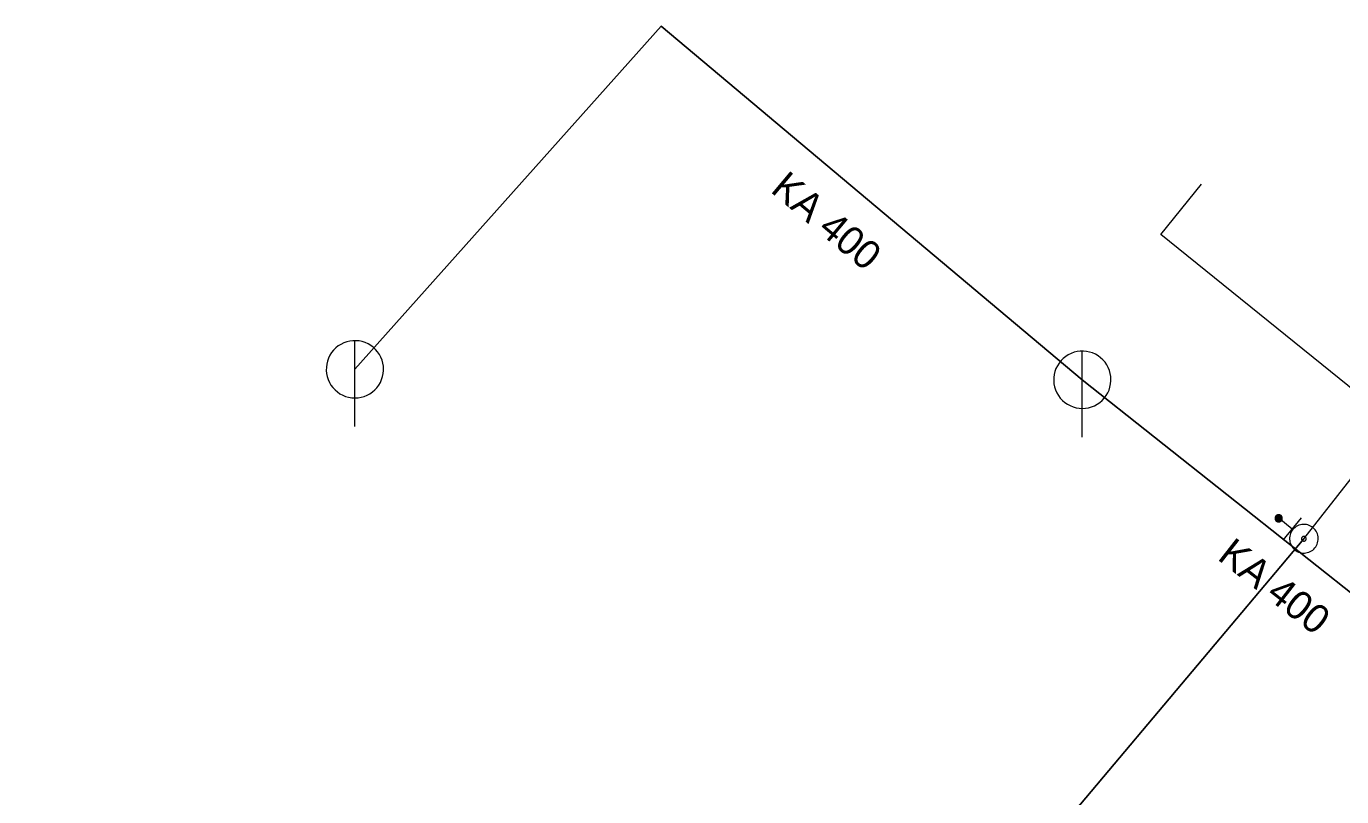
# Model space of a CAD drawing. Extents: x -790267 to -789874, y -989766 to -989454.
# Drawn here: x -790096.36 to -790050.43, y -989612.05 to -989585.16 of the extents above; entities that cross this region are included whole.
import ezdxf

# ---------------------------------------------------------------- set-up
doc = ezdxf.new("R2010")
doc.units = 0
doc.header["$LTSCALE"] = 0.4
doc.layers.add('1', color=7, linetype='Continuous')
for name, color, linetype, lineweight in [('13', 7, 'Continuous', 13), ('14', 7, 'Continuous', 13), ('17', 7, 'Continuous', 25), ('22', 7, 'Continuous', 13), ('34', 7, 'Continuous', 13), ('47', 7, 'Continuous', 13), ('9', 7, 'Continuous', 13)]:
    doc.layers.add(name, color=color, linetype=linetype, lineweight=lineweight)

msp = doc.modelspace()

# ---------------------------------------------------------------- linework, layer by layer
at = {"layer": '13'}
msp.add_lwpolyline([(-790051.752, -989603.049), (-790049.974, -989600.778), (-790048.645, -989598.973), (-790056.749, -989592.432), (-790055.327, -989590.667)], dxfattribs=at)
at = {"layer": '14', "lineweight": 25}
msp.add_line((-790059.488, -989597.498), (-790042.959, -989610.625), dxfattribs=at)
at = {"layer": '14'}
msp.add_line((-790052.165, -989602.709), (-790052.631, -989602.336), dxfattribs=at)
at = {"layer": '14', "lineweight": 25}
msp.add_lwpolyline([(-790084.884, -989597.134), (-790074.188, -989585.16), (-790059.488, -989597.498)], dxfattribs=at)
at = {"layer": '17'}
msp.add_lwpolyline([(-790096.357, -989656.872), (-790069.419, -989624.331), (-790067.352, -989621.572), (-790051.752, -989603.049)], dxfattribs=at)
at = {"layer": '22'}
for p, q in [((-790084.884, -989599.134), (-790084.883, -989596.134)), ((-790059.488, -989599.498), (-790059.487, -989596.498))]:
    msp.add_line(p, q, dxfattribs=at)
for points in [[(-790083.884, -989597.134), (-790083.889, -989597.025), (-790083.907, -989596.917), (-790083.937, -989596.811), (-790083.977, -989596.71), (-790084.029, -989596.613), (-790084.091, -989596.523), (-790084.163, -989596.44), (-790084.243, -989596.366), (-790084.331, -989596.3), (-790084.425, -989596.245), (-790084.525, -989596.2), (-790084.63, -989596.167), (-790084.737, -989596.145), (-790084.846, -989596.135), (-790084.956, -989596.137), (-790085.064, -989596.151), (-790085.171, -989596.176), (-790085.274, -989596.213), (-790085.372, -989596.262), (-790085.464, -989596.32), (-790085.55, -989596.389), (-790085.627, -989596.466), (-790085.696, -989596.552), (-790085.755, -989596.644), (-790085.803, -989596.742), (-790085.84, -989596.845), (-790085.866, -989596.952), (-790085.88, -989597.06), (-790085.883, -989597.17), (-790085.873, -989597.279), (-790085.852, -989597.386), (-790085.818, -989597.49), (-790085.774, -989597.59), (-790085.719, -989597.685), (-790085.653, -989597.773), (-790085.579, -989597.853), (-790085.496, -989597.925), (-790085.406, -989597.987), (-790085.31, -989598.039), (-790085.208, -989598.08), (-790085.103, -989598.11), (-790084.995, -989598.128), (-790084.885, -989598.134), (-790084.776, -989598.128), (-790084.668, -989598.11), (-790084.563, -989598.081), (-790084.461, -989598.04), (-790084.364, -989597.988), (-790084.274, -989597.926), (-790084.191, -989597.855), (-790084.116, -989597.775), (-790084.051, -989597.687), (-790083.995, -989597.593), (-790083.951, -989597.493), (-790083.917, -989597.389), (-790083.895, -989597.281), (-790083.885, -989597.172)], [(-790058.488, -989597.498), (-790058.493, -989597.389), (-790058.511, -989597.281), (-790058.541, -989597.175), (-790058.581, -989597.074), (-790058.633, -989596.977), (-790058.695, -989596.887), (-790058.767, -989596.804), (-790058.847, -989596.73), (-790058.935, -989596.664), (-790059.029, -989596.609), (-790059.129, -989596.564), (-790059.234, -989596.531), (-790059.341, -989596.509), (-790059.45, -989596.499), (-790059.56, -989596.501), (-790059.668, -989596.515), (-790059.775, -989596.54), (-790059.878, -989596.577), (-790059.976, -989596.626), (-790060.068, -989596.684), (-790060.154, -989596.753), (-790060.231, -989596.83), (-790060.3, -989596.916), (-790060.359, -989597.008), (-790060.407, -989597.106), (-790060.444, -989597.209), (-790060.47, -989597.316), (-790060.484, -989597.424), (-790060.487, -989597.534), (-790060.477, -989597.643), (-790060.456, -989597.75), (-790060.422, -989597.854), (-790060.378, -989597.954), (-790060.323, -989598.049), (-790060.257, -989598.137), (-790060.183, -989598.217), (-790060.1, -989598.289), (-790060.01, -989598.351), (-790059.914, -989598.403), (-790059.812, -989598.444), (-790059.707, -989598.474), (-790059.599, -989598.492), (-790059.489, -989598.498), (-790059.38, -989598.492), (-790059.272, -989598.474), (-790059.167, -989598.445), (-790059.065, -989598.404), (-790058.968, -989598.352), (-790058.878, -989598.29), (-790058.795, -989598.219), (-790058.72, -989598.139), (-790058.655, -989598.051), (-790058.599, -989597.957), (-790058.555, -989597.857), (-790058.521, -989597.753), (-790058.499, -989597.645), (-790058.489, -989597.536)]]:
    msp.add_lwpolyline(points, close=True, dxfattribs=at)
at = {"layer": '34'}
msp.add_line((-790051.848, -989602.322), (-790052.482, -989603.095), dxfattribs=at)
at = {"layer": '47'}
for points in [[(-790051.429, -989602.666), (-790051.471, -989602.635), (-790051.516, -989602.607), (-790051.563, -989602.586), (-790051.612, -989602.568), (-790051.664, -989602.556), (-790051.716, -989602.55), (-790051.768, -989602.55), (-790051.82, -989602.554), (-790051.871, -989602.563), (-790051.922, -989602.578), (-790051.97, -989602.599), (-790052.016, -989602.625), (-790052.059, -989602.654), (-790052.098, -989602.689), (-790052.134, -989602.726), (-790052.165, -989602.768), (-790052.193, -989602.813), (-790052.215, -989602.861), (-790052.232, -989602.909), (-790052.244, -989602.961), (-790052.25, -989603.013), (-790052.251, -989603.066), (-790052.247, -989603.118), (-790052.237, -989603.169), (-790052.222, -989603.219), (-790052.201, -989603.267), (-790052.176, -989603.313), (-790052.146, -989603.356), (-790052.111, -989603.395), (-790052.074, -989603.431), (-790052.032, -989603.462), (-790051.987, -989603.49), (-790051.94, -989603.512), (-790051.891, -989603.529), (-790051.839, -989603.541), (-790051.788, -989603.548), (-790051.735, -989603.549), (-790051.683, -989603.544), (-790051.631, -989603.534), (-790051.581, -989603.519), (-790051.533, -989603.498), (-790051.487, -989603.474), (-790051.444, -989603.443), (-790051.405, -989603.408), (-790051.369, -989603.371), (-790051.338, -989603.329), (-790051.31, -989603.284), (-790051.288, -989603.237), (-790051.271, -989603.188), (-790051.259, -989603.136), (-790051.252, -989603.085), (-790051.252, -989603.033), (-790051.256, -989602.981), (-790051.266, -989602.929), (-790051.281, -989602.878), (-790051.302, -989602.83), (-790051.327, -989602.785), (-790051.357, -989602.741), (-790051.392, -989602.702)], [(-790051.699, -989602.986), (-790051.706, -989602.98), (-790051.713, -989602.976), (-790051.72, -989602.973), (-790051.728, -989602.97), (-790051.737, -989602.968), (-790051.746, -989602.967), (-790051.754, -989602.966), (-790051.763, -989602.967), (-790051.771, -989602.969), (-790051.779, -989602.971), (-790051.788, -989602.975), (-790051.795, -989602.979), (-790051.802, -989602.984), (-790051.808, -989602.989), (-790051.814, -989602.996), (-790051.82, -989603.003), (-790051.824, -989603.01), (-790051.827, -989603.017), (-790051.83, -989603.025), (-790051.832, -989603.034), (-790051.833, -989603.043), (-790051.834, -989603.051), (-790051.833, -989603.06), (-790051.831, -989603.069), (-790051.829, -989603.076), (-790051.825, -989603.085), (-790051.821, -989603.092), (-790051.816, -989603.099), (-790051.811, -989603.105), (-790051.804, -989603.111), (-790051.797, -989603.117), (-790051.79, -989603.121), (-790051.783, -989603.124), (-790051.775, -989603.127), (-790051.766, -989603.129), (-790051.758, -989603.131), (-790051.749, -989603.131), (-790051.74, -989603.13), (-790051.731, -989603.128), (-790051.724, -989603.126), (-790051.715, -989603.122), (-790051.708, -989603.118), (-790051.701, -989603.113), (-790051.695, -989603.108), (-790051.689, -989603.101), (-790051.683, -989603.094), (-790051.679, -989603.087), (-790051.676, -989603.08), (-790051.673, -989603.072), (-790051.671, -989603.063), (-790051.669, -989603.055), (-790051.669, -989603.046), (-790051.67, -989603.037), (-790051.672, -989603.029), (-790051.674, -989603.021), (-790051.678, -989603.012), (-790051.682, -989603.005), (-790051.687, -989602.998), (-790051.692, -989602.992)]]:
    msp.add_lwpolyline(points, close=True, dxfattribs=at)
at = {"layer": '9'}
for points in [[(-790052.757, -989602.336), (-790052.757, -989602.349), (-790052.755, -989602.362), (-790052.752, -989602.375), (-790052.747, -989602.387), (-790052.741, -989602.399), (-790052.734, -989602.41), (-790052.726, -989602.42), (-790052.716, -989602.43), (-790052.706, -989602.438), (-790052.695, -989602.445), (-790052.683, -989602.451), (-790052.671, -989602.456), (-790052.658, -989602.459), (-790052.645, -989602.461), (-790052.632, -989602.463), (-790052.619, -989602.462), (-790052.606, -989602.46), (-790052.593, -989602.457), (-790052.581, -989602.452), (-790052.569, -989602.446), (-790052.558, -989602.439), (-790052.548, -989602.431), (-790052.538, -989602.421), (-790052.53, -989602.411), (-790052.523, -989602.4), (-790052.517, -989602.388), (-790052.512, -989602.376), (-790052.509, -989602.363), (-790052.507, -989602.35), (-790052.505, -989602.337), (-790052.506, -989602.324), (-790052.508, -989602.311), (-790052.511, -989602.298), (-790052.516, -989602.286), (-790052.522, -989602.274), (-790052.529, -989602.263), (-790052.537, -989602.253), (-790052.547, -989602.243), (-790052.557, -989602.235), (-790052.568, -989602.228), (-790052.58, -989602.222), (-790052.592, -989602.217), (-790052.605, -989602.214), (-790052.618, -989602.212), (-790052.631, -989602.211), (-790052.644, -989602.211), (-790052.657, -989602.213), (-790052.67, -989602.216), (-790052.682, -989602.221), (-790052.694, -989602.227), (-790052.705, -989602.234), (-790052.715, -989602.242), (-790052.725, -989602.252), (-790052.733, -989602.262), (-790052.74, -989602.273), (-790052.746, -989602.285), (-790052.751, -989602.297), (-790052.754, -989602.31), (-790052.756, -989602.323)], [(-790052.737, -989602.336), (-790052.738, -989602.347), (-790052.736, -989602.358), (-790052.733, -989602.369), (-790052.729, -989602.379), (-790052.724, -989602.389), (-790052.718, -989602.398), (-790052.711, -989602.407), (-790052.703, -989602.415), (-790052.694, -989602.422), (-790052.685, -989602.428), (-790052.675, -989602.433), (-790052.665, -989602.437), (-790052.654, -989602.44), (-790052.643, -989602.443), (-790052.632, -989602.443), (-790052.621, -989602.443), (-790052.61, -989602.441), (-790052.599, -989602.438), (-790052.589, -989602.434), (-790052.579, -989602.429), (-790052.57, -989602.423), (-790052.561, -989602.416), (-790052.553, -989602.408), (-790052.546, -989602.399), (-790052.54, -989602.39), (-790052.535, -989602.38), (-790052.531, -989602.37), (-790052.528, -989602.359), (-790052.526, -989602.348), (-790052.525, -989602.337), (-790052.525, -989602.326), (-790052.527, -989602.315), (-790052.53, -989602.304), (-790052.534, -989602.294), (-790052.539, -989602.284), (-790052.545, -989602.275), (-790052.552, -989602.266), (-790052.56, -989602.258), (-790052.569, -989602.251), (-790052.578, -989602.245), (-790052.588, -989602.24), (-790052.598, -989602.236), (-790052.609, -989602.233), (-790052.62, -989602.231), (-790052.631, -989602.231), (-790052.642, -989602.23), (-790052.653, -989602.232), (-790052.664, -989602.235), (-790052.674, -989602.239), (-790052.684, -989602.244), (-790052.693, -989602.25), (-790052.702, -989602.257), (-790052.71, -989602.265), (-790052.717, -989602.274), (-790052.723, -989602.283), (-790052.728, -989602.293), (-790052.732, -989602.303), (-790052.735, -989602.314), (-790052.737, -989602.325)], [(-790052.718, -989602.336), (-790052.718, -989602.345), (-790052.717, -989602.354), (-790052.714, -989602.363), (-790052.711, -989602.371), (-790052.707, -989602.379), (-790052.702, -989602.387), (-790052.696, -989602.394), (-790052.69, -989602.4), (-790052.683, -989602.406), (-790052.675, -989602.411), (-790052.667, -989602.415), (-790052.659, -989602.418), (-790052.65, -989602.421), (-790052.641, -989602.422), (-790052.632, -989602.424), (-790052.623, -989602.423), (-790052.614, -989602.422), (-790052.605, -989602.419), (-790052.597, -989602.416), (-790052.589, -989602.412), (-790052.581, -989602.407), (-790052.574, -989602.401), (-790052.568, -989602.395), (-790052.562, -989602.388), (-790052.557, -989602.38), (-790052.553, -989602.372), (-790052.55, -989602.364), (-790052.547, -989602.355), (-790052.546, -989602.346), (-790052.544, -989602.337), (-790052.545, -989602.328), (-790052.546, -989602.319), (-790052.549, -989602.31), (-790052.552, -989602.302), (-790052.556, -989602.294), (-790052.561, -989602.286), (-790052.567, -989602.279), (-790052.573, -989602.273), (-790052.58, -989602.267), (-790052.588, -989602.262), (-790052.596, -989602.258), (-790052.604, -989602.255), (-790052.613, -989602.252), (-790052.622, -989602.251), (-790052.631, -989602.25), (-790052.64, -989602.25), (-790052.649, -989602.251), (-790052.658, -989602.254), (-790052.666, -989602.257), (-790052.674, -989602.261), (-790052.682, -989602.266), (-790052.689, -989602.272), (-790052.695, -989602.278), (-790052.701, -989602.285), (-790052.706, -989602.293), (-790052.71, -989602.301), (-790052.713, -989602.309), (-790052.716, -989602.318), (-790052.717, -989602.327)], [(-790052.698, -989602.336), (-790052.698, -989602.343), (-790052.697, -989602.35), (-790052.696, -989602.357), (-790052.693, -989602.363), (-790052.69, -989602.369), (-790052.686, -989602.375), (-790052.682, -989602.381), (-790052.677, -989602.386), (-790052.671, -989602.39), (-790052.665, -989602.394), (-790052.659, -989602.397), (-790052.653, -989602.4), (-790052.646, -989602.401), (-790052.639, -989602.404), (-790052.632, -989602.404), (-790052.625, -989602.404), (-790052.618, -989602.402), (-790052.611, -989602.401), (-790052.605, -989602.398), (-790052.598, -989602.395), (-790052.593, -989602.391), (-790052.587, -989602.387), (-790052.582, -989602.382), (-790052.578, -989602.376), (-790052.574, -989602.37), (-790052.571, -989602.364), (-790052.568, -989602.358), (-790052.566, -989602.351), (-790052.565, -989602.344), (-790052.564, -989602.337), (-790052.564, -989602.33), (-790052.565, -989602.323), (-790052.567, -989602.316), (-790052.57, -989602.31), (-790052.573, -989602.303), (-790052.577, -989602.298), (-790052.581, -989602.292), (-790052.586, -989602.287), (-790052.592, -989602.283), (-790052.597, -989602.279), (-790052.604, -989602.276), (-790052.61, -989602.273), (-790052.617, -989602.271), (-790052.624, -989602.27), (-790052.631, -989602.27), (-790052.638, -989602.27), (-790052.645, -989602.27), (-790052.652, -989602.272), (-790052.658, -989602.275), (-790052.664, -989602.278), (-790052.67, -989602.282), (-790052.676, -989602.286), (-790052.681, -989602.291), (-790052.685, -989602.297), (-790052.689, -989602.302), (-790052.692, -989602.309), (-790052.695, -989602.315), (-790052.696, -989602.322), (-790052.698, -989602.329)], [(-790052.678, -989602.336), (-790052.678, -989602.341), (-790052.678, -989602.346), (-790052.677, -989602.351), (-790052.675, -989602.355), (-790052.673, -989602.36), (-790052.67, -989602.364), (-790052.667, -989602.367), (-790052.663, -989602.371), (-790052.66, -989602.374), (-790052.656, -989602.377), (-790052.651, -989602.379), (-790052.647, -989602.381), (-790052.642, -989602.382), (-790052.637, -989602.384), (-790052.632, -989602.384), (-790052.627, -989602.384), (-790052.622, -989602.383), (-790052.617, -989602.382), (-790052.613, -989602.38), (-790052.608, -989602.378), (-790052.604, -989602.375), (-790052.6, -989602.372), (-790052.597, -989602.368), (-790052.594, -989602.365), (-790052.591, -989602.361), (-790052.589, -989602.356), (-790052.587, -989602.352), (-790052.586, -989602.347), (-790052.585, -989602.342), (-790052.584, -989602.337), (-790052.584, -989602.332), (-790052.585, -989602.327), (-790052.586, -989602.322), (-790052.588, -989602.318), (-790052.59, -989602.313), (-790052.593, -989602.309), (-790052.596, -989602.305), (-790052.599, -989602.302), (-790052.603, -989602.299), (-790052.607, -989602.296), (-790052.612, -989602.294), (-790052.616, -989602.292), (-790052.621, -989602.291), (-790052.626, -989602.29), (-790052.631, -989602.29), (-790052.636, -989602.29), (-790052.641, -989602.291), (-790052.646, -989602.291), (-790052.65, -989602.293), (-790052.655, -989602.295), (-790052.659, -989602.298), (-790052.662, -989602.301), (-790052.666, -989602.304), (-790052.669, -989602.308), (-790052.672, -989602.312), (-790052.674, -989602.317), (-790052.676, -989602.321), (-790052.677, -989602.326), (-790052.678, -989602.331)], [(-790052.658, -989602.336), (-790052.658, -989602.339), (-790052.659, -989602.342), (-790052.658, -989602.344), (-790052.657, -989602.347), (-790052.656, -989602.35), (-790052.654, -989602.352), (-790052.652, -989602.354), (-790052.65, -989602.356), (-790052.648, -989602.358), (-790052.646, -989602.36), (-790052.643, -989602.362), (-790052.64, -989602.363), (-790052.638, -989602.363), (-790052.635, -989602.364), (-790052.632, -989602.364), (-790052.629, -989602.364), (-790052.626, -989602.364), (-790052.623, -989602.363), (-790052.621, -989602.362), (-790052.618, -989602.361), (-790052.616, -989602.359), (-790052.613, -989602.357), (-790052.611, -989602.355), (-790052.61, -989602.353), (-790052.608, -989602.351), (-790052.607, -989602.348), (-790052.605, -989602.345), (-790052.605, -989602.343), (-790052.604, -989602.34), (-790052.603, -989602.337), (-790052.604, -989602.334), (-790052.604, -989602.331), (-790052.605, -989602.328), (-790052.606, -989602.326), (-790052.607, -989602.323), (-790052.609, -989602.321), (-790052.61, -989602.318), (-790052.612, -989602.316), (-790052.615, -989602.315), (-790052.617, -989602.313), (-790052.62, -989602.312), (-790052.622, -989602.311), (-790052.625, -989602.31), (-790052.628, -989602.31), (-790052.631, -989602.309), (-790052.634, -989602.31), (-790052.637, -989602.309), (-790052.639, -989602.311), (-790052.642, -989602.311), (-790052.645, -989602.312), (-790052.647, -989602.314), (-790052.649, -989602.315), (-790052.651, -989602.317), (-790052.653, -989602.32), (-790052.655, -989602.322), (-790052.656, -989602.325), (-790052.657, -989602.327), (-790052.658, -989602.33), (-790052.658, -989602.333)], [(-790052.639, -989602.336), (-790052.639, -989602.338), (-790052.639, -989602.338), (-790052.638, -989602.338), (-790052.638, -989602.34), (-790052.639, -989602.341), (-790052.637, -989602.341), (-790052.637, -989602.341), (-790052.637, -989602.343), (-790052.637, -989602.343), (-790052.636, -989602.344), (-790052.634, -989602.344), (-790052.634, -989602.344), (-790052.634, -989602.345), (-790052.632, -989602.345), (-790052.632, -989602.345), (-790052.631, -989602.345), (-790052.63, -989602.345), (-790052.63, -989602.344), (-790052.629, -989602.344), (-790052.627, -989602.344), (-790052.627, -989602.343), (-790052.627, -989602.343), (-790052.626, -989602.342), (-790052.626, -989602.342), (-790052.624, -989602.341), (-790052.624, -989602.34), (-790052.623, -989602.339), (-790052.623, -989602.339), (-790052.623, -989602.338), (-790052.623, -989602.337), (-790052.623, -989602.336), (-790052.623, -989602.335), (-790052.623, -989602.335), (-790052.624, -989602.334), (-790052.624, -989602.333), (-790052.625, -989602.332), (-790052.625, -989602.332), (-790052.626, -989602.331), (-790052.626, -989602.331), (-790052.627, -989602.33), (-790052.628, -989602.33), (-790052.629, -989602.329), (-790052.629, -989602.329), (-790052.63, -989602.329), (-790052.631, -989602.329), (-790052.632, -989602.329), (-790052.633, -989602.329), (-790052.633, -989602.329), (-790052.634, -989602.33), (-790052.635, -989602.329), (-790052.636, -989602.331), (-790052.636, -989602.331), (-790052.637, -989602.331), (-790052.637, -989602.331), (-790052.638, -989602.333), (-790052.638, -989602.334), (-790052.638, -989602.335), (-790052.639, -989602.335), (-790052.639, -989602.336)]]:
    msp.add_lwpolyline(points, close=True, dxfattribs=at)

# ---------------------------------------------------------------- texts
at = {"layer": '1'}
for rotation, p in [(320, (-790070.411, -989590.92)), (322, (-790054.807, -989603.749))]:
    msp.add_text('KA 400', height=1, rotation=rotation, dxfattribs=at).set_placement(p)

doc.saveas('drawing.dxf')
